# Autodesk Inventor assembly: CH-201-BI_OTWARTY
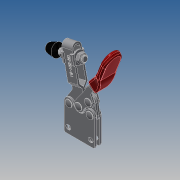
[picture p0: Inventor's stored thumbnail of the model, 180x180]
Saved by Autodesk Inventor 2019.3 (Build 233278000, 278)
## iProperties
Company: ·L?¤¤?
Created: 2010-06
Part Number: CH-201-BI_OTWARTY
Material: Ogólny
Description: STEP AP203
Document SubType Name: Assembly
Designer: CADENGINEERING4
Sending System: SolidWorks 2005179
Preprocessor: SwSTEP 2.0
Title: CH-201-BI.STEP
Author: ·L?¥Î?
Revision Number: ANY
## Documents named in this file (9)
- E:\STRONA\Horizontal toggle clamp\CH-201-BI\CH-201-BI_OTWARTY.iam
- E:\STRONA\Horizontal toggle clamp\CH-201-BI\14134-02___.ipt
- E:\STRONA\Horizontal toggle clamp\CH-201-BI\201-B-04___.ipt
- E:\STRONA\Horizontal toggle clamp\CH-201-BI\201-B-06___.ipt
- E:\STRONA\Horizontal toggle clamp\CH-201-BI\201-BI-02___.ipt
- E:\STRONA\Horizontal toggle clamp\CH-201-BI\FW140___.ipt
- E:\STRONA\Horizontal toggle clamp\CH-201-BI\14134___.ipt
- E:\STRONA\Horizontal toggle clamp\CH-201-BI\201-B___.iam
- E:\STRONA\Horizontal toggle clamp\CH-201-BI\201-BI-01___.ipt
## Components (14 placed, 14 different names)
1. 14134-02_??_1 — Równoległe:3, Zestawiające:1, Zestawiające:5
2. 201-B-04_??_2 — Zestawiające:11, Zestawiające:12, Zestawiające:13
3. 201-B-06_??_3 — Zestawiające:20, Zestawiające:21
4. 201-BI-02_??_4 — Równoległe:1, Zestawiające:7, Zestawiające:8, Zestawiające:9, Zestawiające:10, Zestawiające:22, Zestawiające:25, Zestawiające:26
5. FW140_??_5 — Równoległe:2, Zestawiające:2, Zestawiające:6, Zestawiające:7
6. 14134_??_6 — Równoległe:3, Zestawiające:1, Zestawiające:2, Zestawiające:3, Zestawiające:4, Zestawiające:9
7. 201-B-06_??_7 — Zestawiające:16, Zestawiające:17
8. 201-B-04_??_8 — Zestawiające:11, Zestawiające:12, Zestawiające:13, Zestawiające:14, Zestawiające:15, Zestawiające:18, Zestawiające:19
9. 201-B_??_9 [sub-assembly] — Zestawiające:18, Zestawiające:19, Zestawiające:20, Zestawiające:21, Zestawiające:26, Zestawiające:27, Przejściowe:1
10. 14134-02_??_10 — Zestawiające:3, Zestawiające:6
11. FW140_??_11 — Równoległe:1, Równoległe:2, Zestawiające:4, Zestawiające:5, Zestawiające:8
12. 201-B-06_??_12 — Zestawiające:10, Zestawiające:27
13. 201-B-06_??_13 — Zestawiające:22, Zestawiające:23, Zestawiające:24
14. 201-BI-01_??_14 — Zestawiające:14, Zestawiające:15, Zestawiające:16, Zestawiające:17, Zestawiające:23, Zestawiające:24, Zestawiające:25, Przejściowe:1
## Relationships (31: Mate 27, Flush 3, Transitional 1)
- Równoległe:1 [Flush]: 201-BI-02_??_4 ↔ FW140_??_11
- Równoległe:2 [Flush]: FW140_??_5 ↔ FW140_??_11
- Równoległe:3 [Flush]: 14134-02_??_1 ↔ 14134_??_6
- Zestawiające:1 [Mate]: 14134-02_??_1 ↔ 14134_??_6
- Zestawiające:2 [Mate]: FW140_??_5 ↔ 14134_??_6
- Zestawiające:3 [Mate]: 14134_??_6 ↔ 14134-02_??_10
- Zestawiające:4 [Mate]: 14134_??_6 ↔ FW140_??_11
- Zestawiające:5 [Mate]: 14134-02_??_1 ↔ FW140_??_11
- Zestawiające:6 [Mate]: FW140_??_5 ↔ 14134-02_??_10
- Zestawiające:7 [Mate]: 201-BI-02_??_4 ↔ FW140_??_5
- Zestawiające:8 [Mate]: 201-BI-02_??_4 ↔ FW140_??_11
- Zestawiające:9 [Mate]: 201-BI-02_??_4 ↔ 14134_??_6
- Zestawiające:10 [Mate]: 201-BI-02_??_4 ↔ 201-B-06_??_12
- Zestawiające:11 [Mate]: 201-B-04_??_2 ↔ 201-B-04_??_8
- Zestawiające:12 [Mate]: 201-B-04_??_2 ↔ 201-B-04_??_8
- Zestawiające:13 [Mate]: 201-B-04_??_2 ↔ 201-B-04_??_8
- Zestawiające:14 [Mate]: 201-B-04_??_8 ↔ 201-BI-01_??_14
- Zestawiające:15 [Mate]: 201-B-04_??_8 ↔ 201-BI-01_??_14
- Zestawiające:16 [Mate]: 201-B-06_??_7 ↔ 201-BI-01_??_14
- Zestawiające:17 [Mate]: 201-B-06_??_7 ↔ 201-BI-01_??_14
- Zestawiające:18 [Mate]: 201-B-04_??_8 ↔ 201-B_??_9
- Zestawiające:19 [Mate]: 201-B-04_??_8 ↔ 201-B_??_9
- Zestawiające:20 [Mate]: 201-B-06_??_3 ↔ 201-B_??_9
- Zestawiające:21 [Mate]: 201-B-06_??_3 ↔ 201-B_??_9
- Zestawiające:22 [Mate]: 201-BI-02_??_4 ↔ 201-B-06_??_13
- Zestawiające:23 [Mate]: 201-B-06_??_13 ↔ 201-BI-01_??_14
- Zestawiające:24 [Mate]: 201-B-06_??_13 ↔ 201-BI-01_??_14
- Zestawiające:25 [Mate]: 201-BI-02_??_4 ↔ 201-BI-01_??_14
- Zestawiające:26 [Mate]: 201-BI-02_??_4 ↔ 201-B_??_9
- Zestawiające:27 [Mate]: 201-B_??_9 ↔ 201-B-06_??_12
- Przejściowe:1 [Transitional]: 201-B_??_9 ↔ 201-BI-01_??_14
